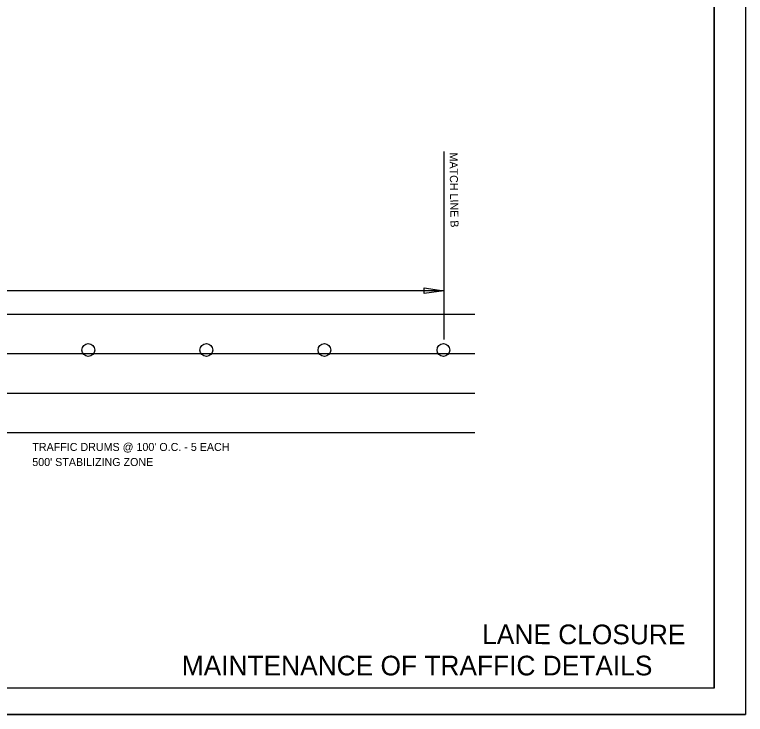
# Model space of a CAD drawing. Extents: x 1397271 to 1411271, y 376395 to 377888.
# Drawn here: x 1405825 to 1406605, y 376395 to 377141 of the extents above; entities that cross this region are included whole.
import ezdxf

# ---------------------------------------------------------------- set-up
doc = ezdxf.new("R2010")
doc.units = 0
for name, color, linetype in [('Default', 7, 'Continuous'), ('R_Border', 7, 'Continuous'), ('R_MOT', 7, 'Continuous'), ('R_No Plot', 7, 'Continuous')]:
    doc.layers.add(name, color=color, linetype=linetype)

msp = doc.modelspace()

# ---------------------------------------------------------------- linework, layer by layer
at = {"layer": 'Default'}
for p, q in [((1406282.56, 376995.07), (1406282.56, 376794.66)), ((1406261.54, 376843.55), (1406261.54, 376849.86)), ((1406261.54, 376849.86), (1406282.56, 376846.71)), ((1406282.56, 376846.71), (1405652.04, 376846.71)), ((1406282.56, 376846.71), (1406261.54, 376843.55)), ((1404559.15, 376821.56), (1406315.82, 376821.56)), ((1404559.15, 376779.52), (1406315.82, 376779.52)), ((1404559.15, 376737.49), (1406315.82, 376737.49)), ((1404559.15, 376695.46), (1406315.82, 376695.46))]:
    msp.add_line(p, q, dxfattribs=at)
at = {"layer": 'R_Border'}
for q in [(1406571.3, 377860.72), (1404358, 376422.47)]:
    msp.add_line((1406571.3, 376422.47), q, dxfattribs=at)
at = {"layer": 'R_MOT'}
for centre in [(1405903.17, 376783.4), (1406029.17, 376783.4), (1406155.17, 376783.4), (1406282.28, 376783.4)]:
    msp.add_circle(centre, 6.8, dxfattribs=at)
at = {"layer": 'R_No Plot'}
msp.add_line((1404271.19, 376394.62), (1406604.57, 376394.62), dxfattribs=at)
for points in [[(1404271.14, 377887.98), (1406604.57, 377887.98), (1406604.57, 376394.59), (1404271.14, 376394.59)], [(1405995.47, 377860.72), (1405995.47, 377791.56), (1406245.6, 377791.56), (1406245.6, 377771.12), (1406408, 377771.12), (1406408, 377600.79), (1406571.3, 377600.79), (1406571.3, 376422.47), (1404358, 376422.47), (1404358, 377860.72)]]:
    msp.add_lwpolyline(points, close=True, dxfattribs=at)

# ---------------------------------------------------------------- texts
at = {"layer": 'Default'}
for s, height, rotation, p in [('MATCH LINE B', 8.5402, 270.80593, (1406288.74, 376994.07)), ('LANE CLOSURE', 21.0004, 359.93264, (1406323.6, 376469.59))]:
    msp.add_text(s, height=height, rotation=rotation, dxfattribs=at).set_placement(p)
for s, p in [("TRAFFIC DRUMS @ 100' O.C. - 5 EACH", (1405843.39, 376675.68)), ("500' STABILIZING ZONE", (1405843.39, 376659.6))]:
    msp.add_text(s, height=8.5402, dxfattribs=at).set_placement(p)
at = {"layer": 'R_Border'}
msp.add_text('MAINTENANCE OF TRAFFIC DETAILS', height=21.0004, rotation=360, dxfattribs=at).set_placement((1406002.91, 376436.19))

doc.saveas('drawing.dxf')
